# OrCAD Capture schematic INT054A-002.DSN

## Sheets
1 PAGE1: title: TUSB544RNQEVM INT054-002; rev: A
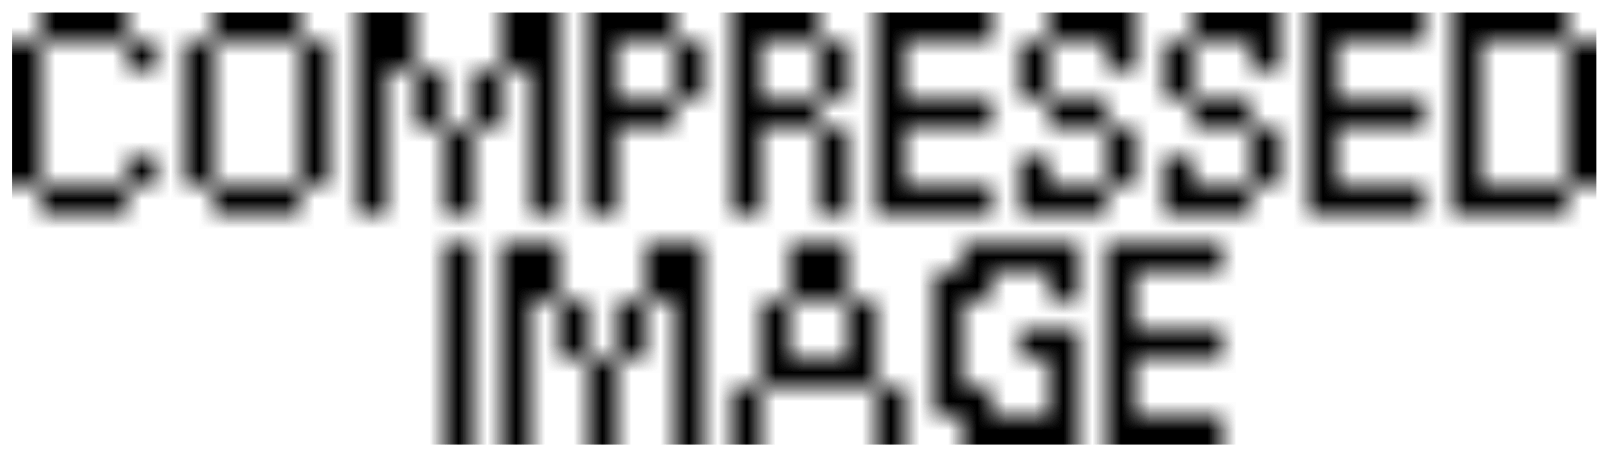
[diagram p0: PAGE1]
2 PAGE2: size C
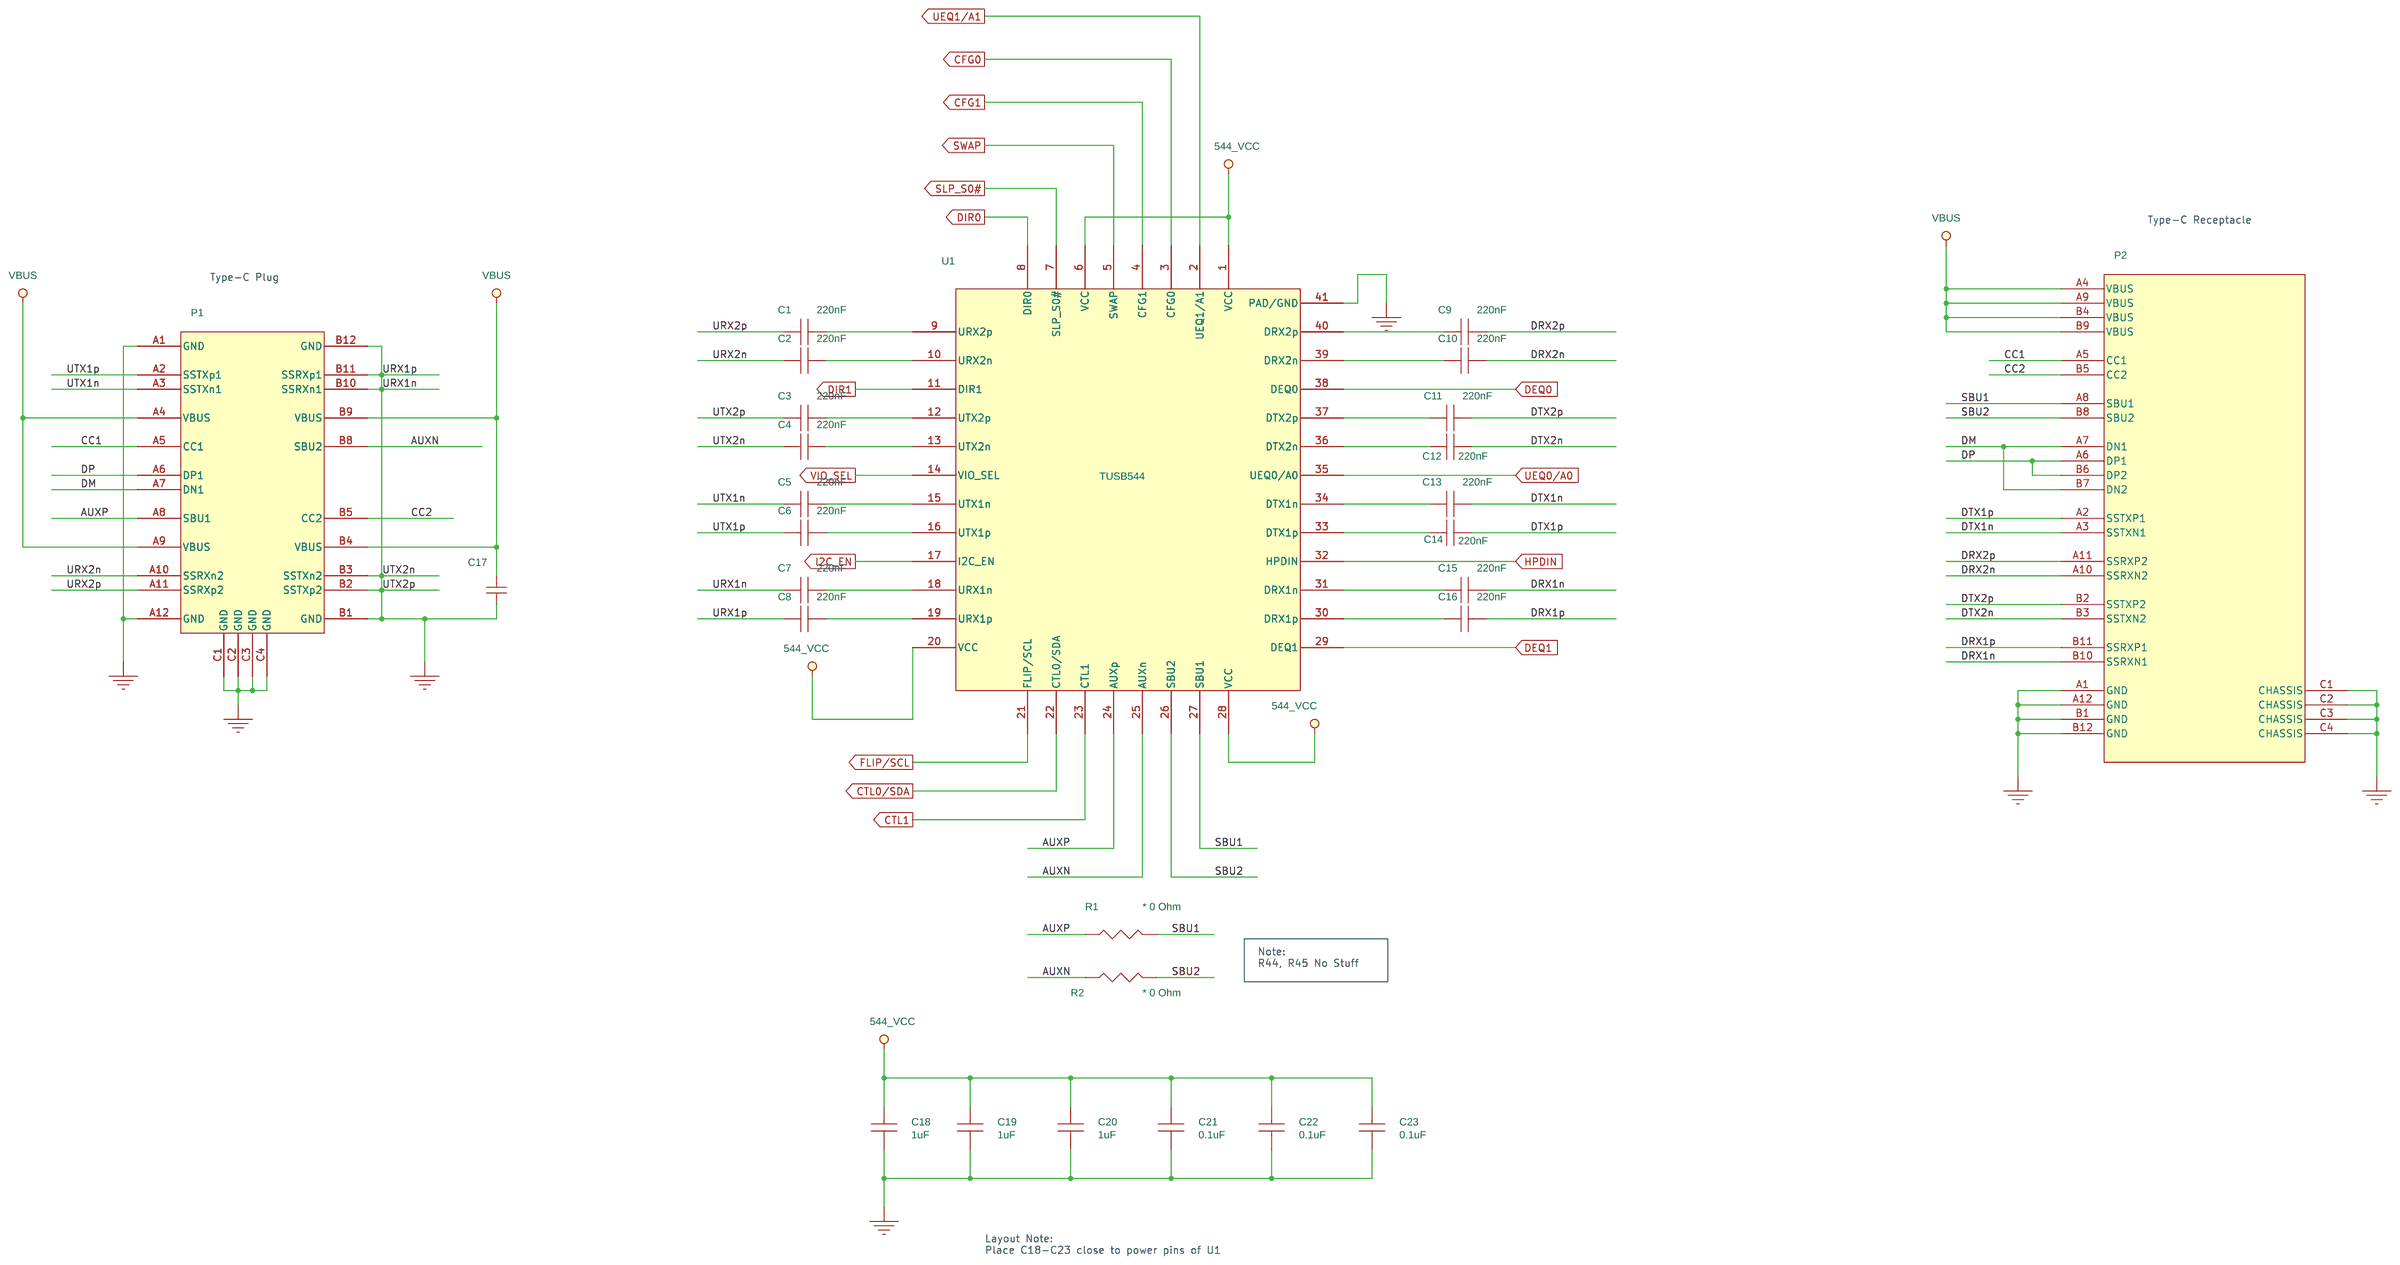
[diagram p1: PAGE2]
3 PAGE3: size C
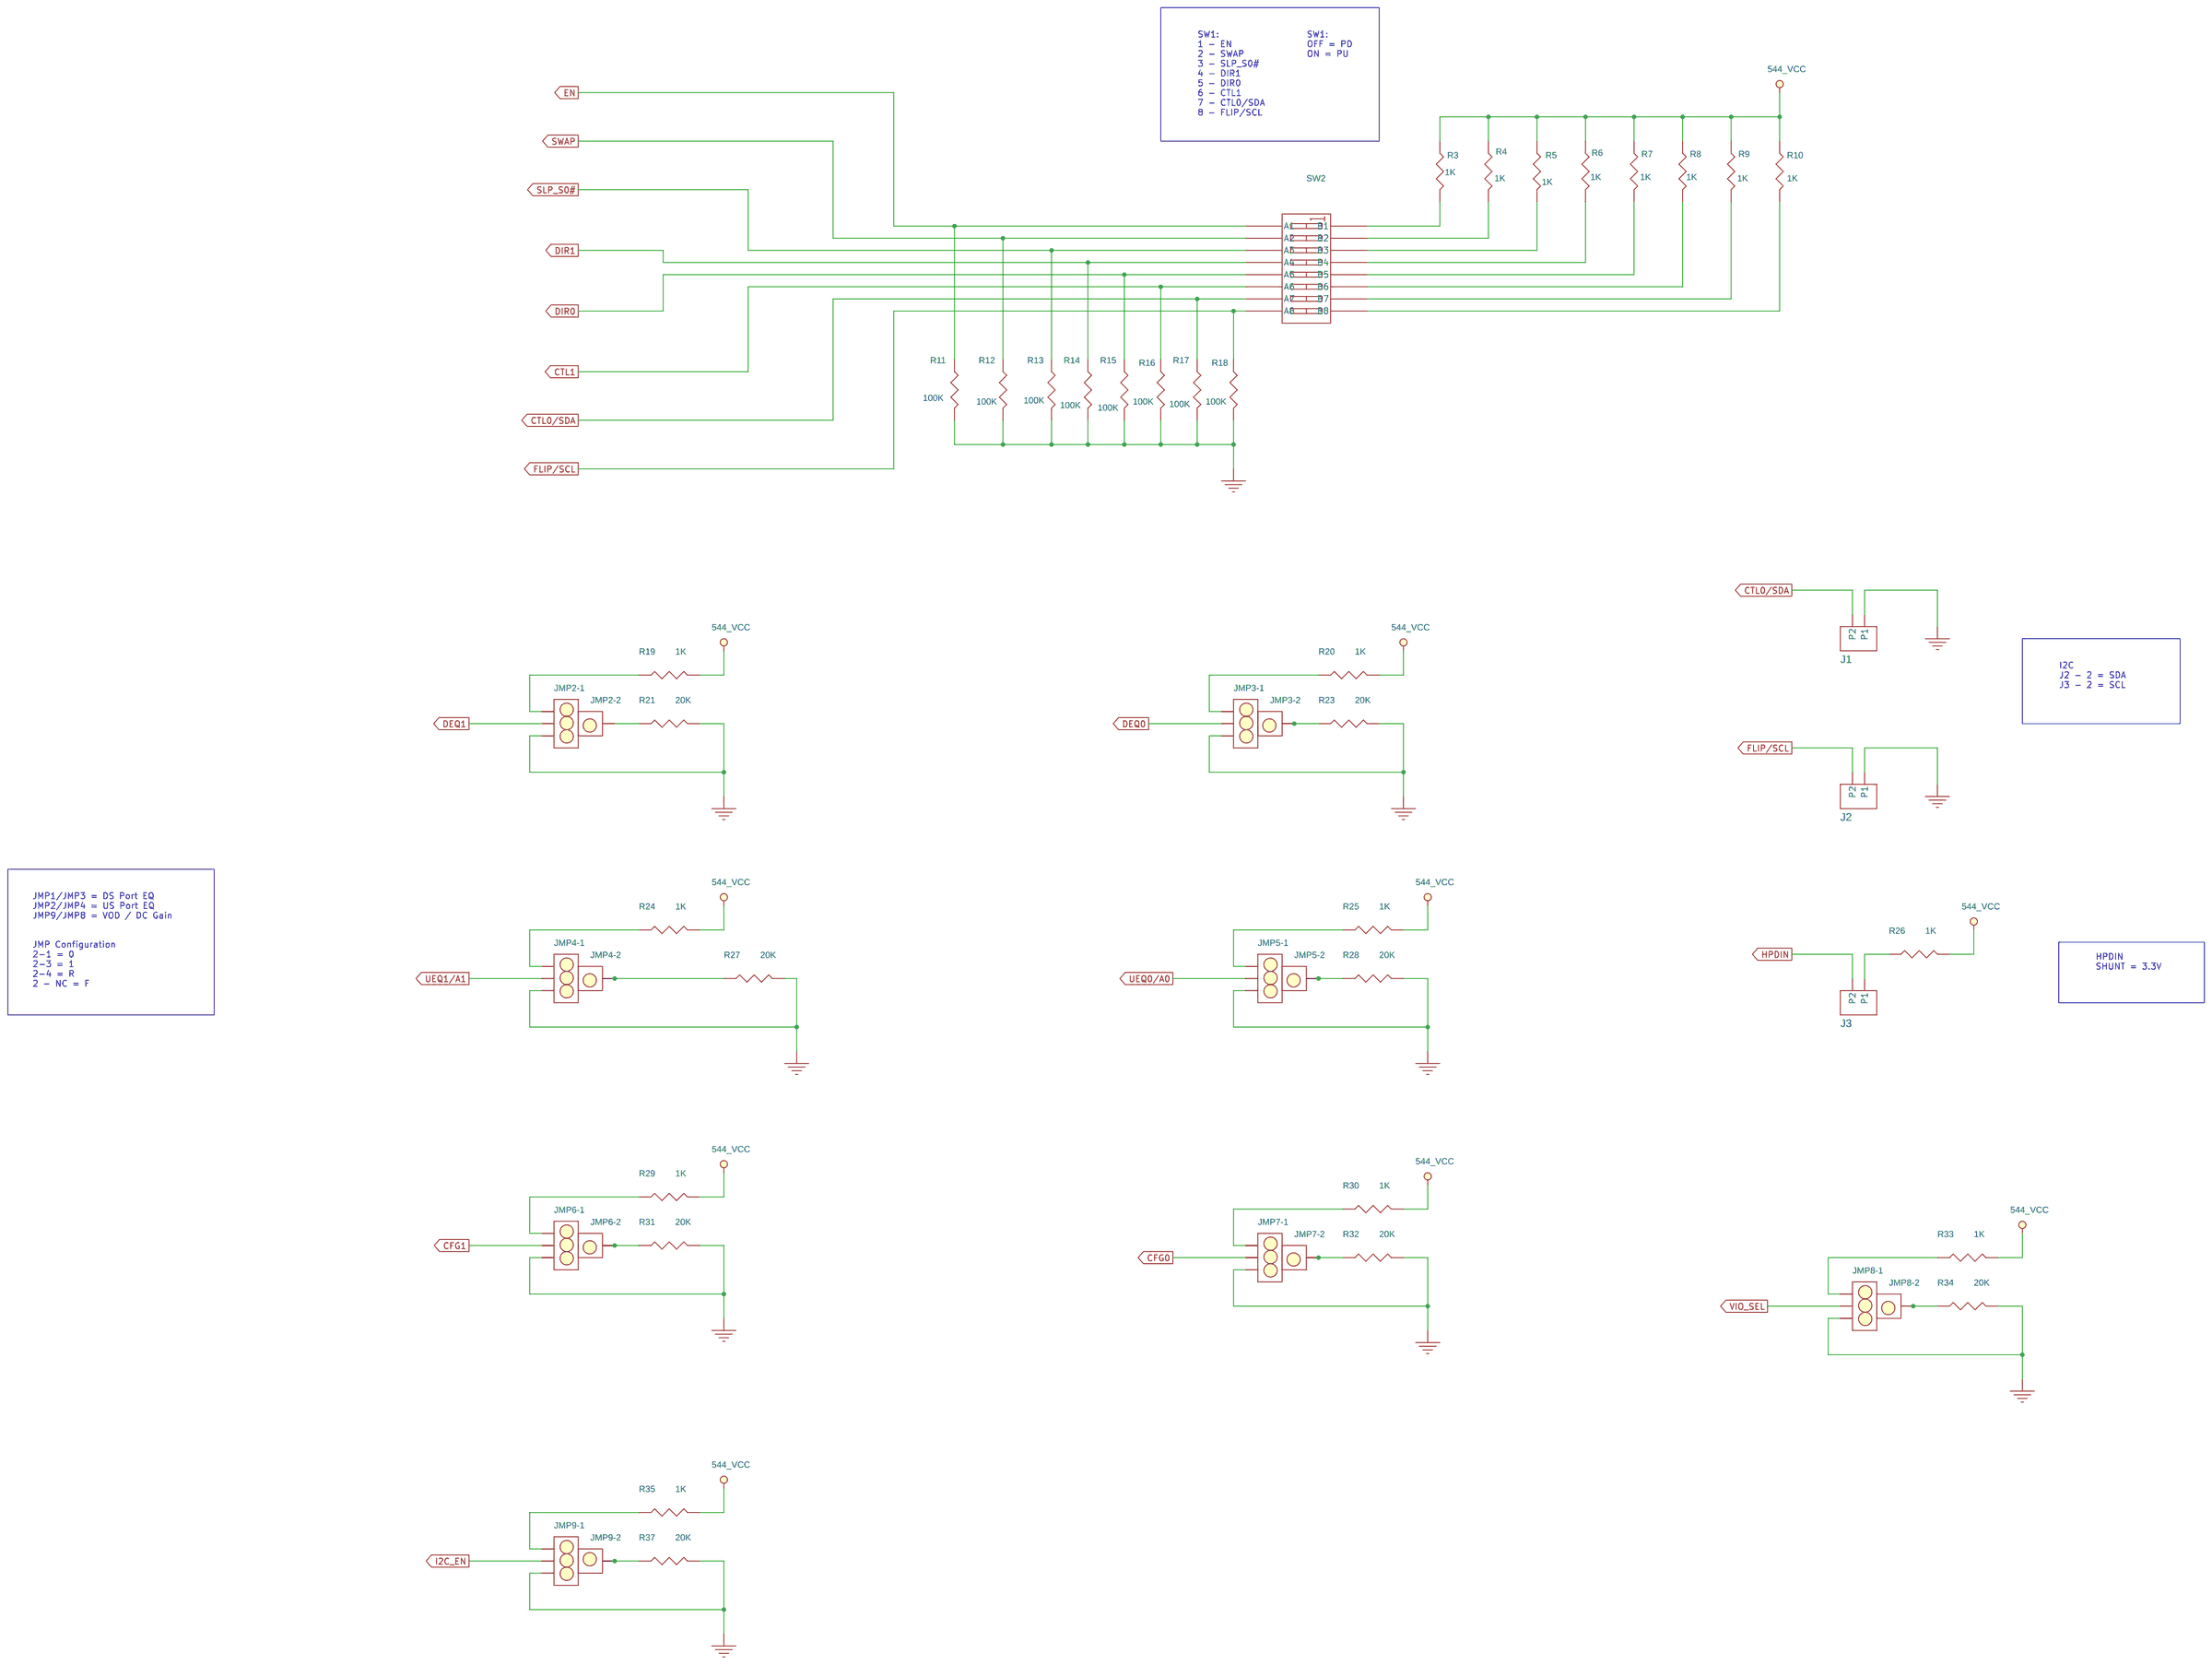
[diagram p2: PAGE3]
4 PAGE4: size C
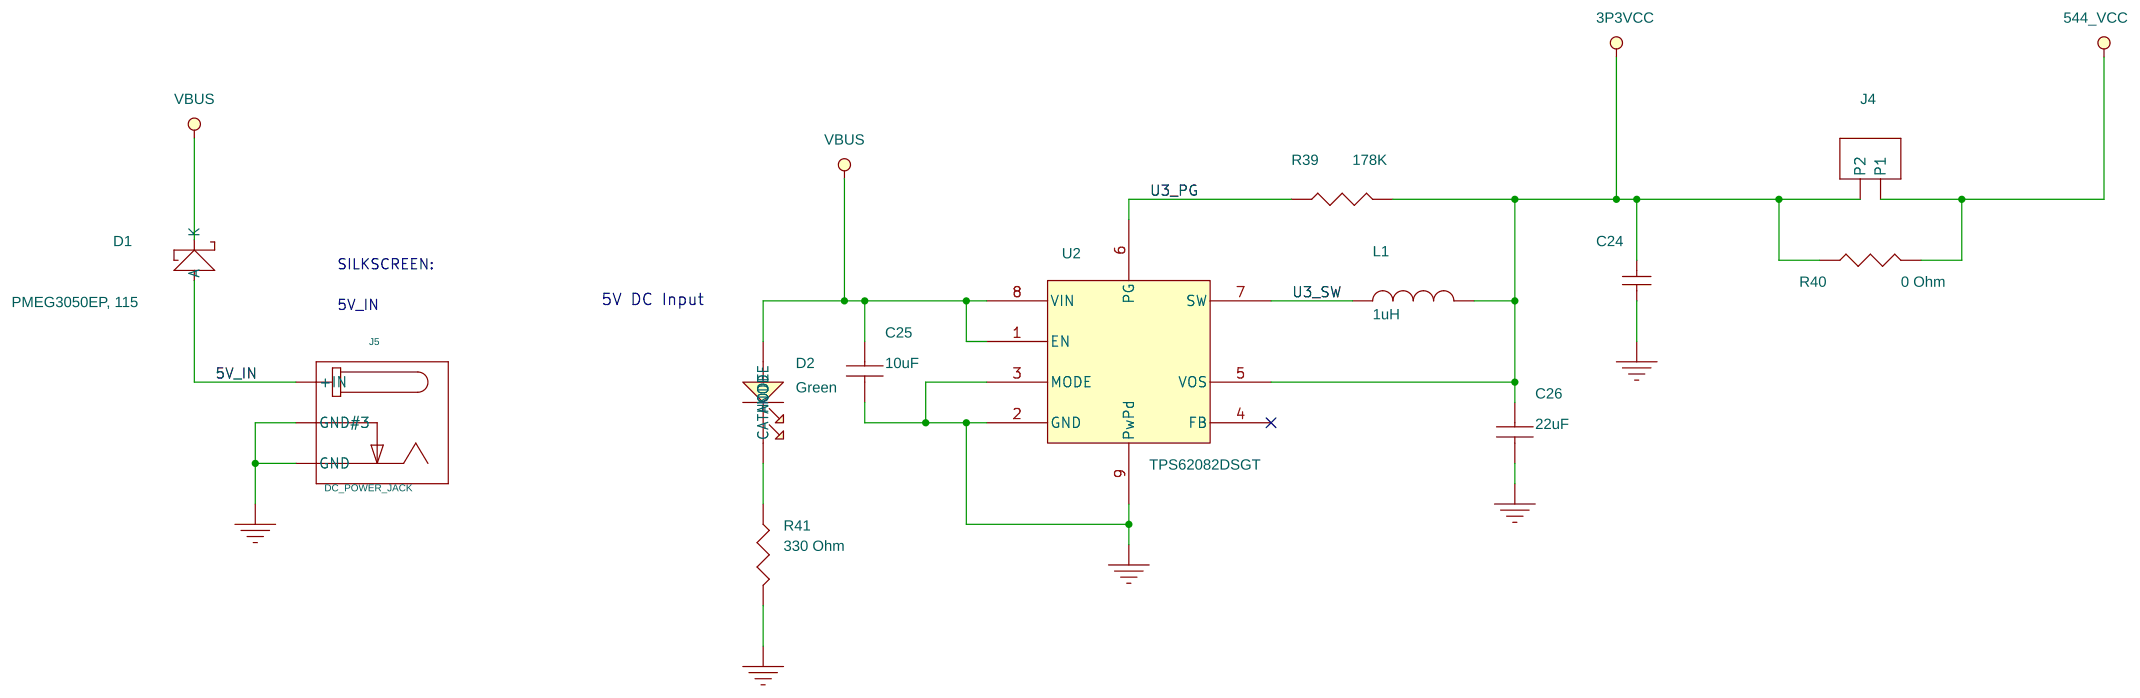
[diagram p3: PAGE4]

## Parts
sheet PAGE2
C1  220nF  [cc0201]
C2  220nF  [cc0201]
C3  220nF  [cc0201]
C4  220nF  [cc0201]
C5  220nF  [cc0201]
C6  220nF  [cc0201]
C7  220nF  [cc0201]
C8  220nF  [cc0201]
C9  220nF  [cc0201]
C10  220nF  [cc0201]
C11  220nF  [cc0201]
C12  220nF  [cc0201]
C13  220nF  [cc0201]
C14  220nF  [cc0201]
C15  220nF  [cc0201]
C16  220nF  [cc0201]
C17  10uF  [0805]
C18  1uF  [cc0402]
C19  1uF  [cc0402]
C20  1uF  [cc0402]
C21  0.1uF  [cc0402]
C22  0.1uF  [cc0402]
C23  0.1uF  [cc0402]
P1  Wurth 632712000021  [USB-C_SMRT_632_712_000_021]
P2  JAE DX07S024JJ2  [USB-C_SMRT_DX07S024JJ2]
R1  * 0 Ohm  [r0402]
R2  * 0 Ohm  [r0402]
U1  TUSB544  [SKT_IRONWOOD_C14861_QFN-40]
sheet PAGE3
J1  CON02  [HDR_THVT_1x2_100_M]
J2  CON02  [HDR_THVT_1x2_100_M]
J3  CON02  [HDR_THVT_1x2_100_M]
JMP2-1  JMP1x3  [berg1x3]
JMP2-2  JMP1x1  [berg1x1]
JMP3-1  JMP1x3  [berg1x3]
JMP3-2  JMP1x1  [berg1x1]
JMP4-1  JMP1x3  [berg1x3]
JMP4-2  JMP1x1  [berg1x1]
JMP5-1  JMP1x3  [berg1x3]
JMP5-2  JMP1x1  [berg1x1]
JMP6-1  JMP1x3  [berg1x3]
JMP6-2  JMP1x1  [berg1x1]
JMP7-1  JMP1x3  [berg1x3]
JMP7-2  JMP1x1  [berg1x1]
JMP8-1  JMP1x3  [berg1x3]
JMP8-2  JMP1x1  [berg1x1]
JMP9-1  JMP1x3  [berg1x3]
JMP9-2  4 Pin-T Berg Jumper  [berg1x1]
R3  1K  [r0402]
R4  1K  [r0402]
R5  1K  [r0402]
R6  1K  [r0402]
R7  1K  [r0402]
R8  1K  [r0402]
R9  1K  [r0402]
R10  1K  [r0402]
R11  100K  [r0402]
R12  100K  [r0402]
R13  100K  [r0402]
R14  100K  [r0402]
R15  100K  [r0402]
R16  100K  [r0402]
R17  100K  [r0402]
R18  100K  [r0402]
R19  1K  [r0402]
R20  1K  [r0402]
R21  20K  [r0402]
R23  20K  [r0402]
R24  1K  [r0402]
R25  1K  [r0402]
R26  1K  [r0402]
R27  20K  [r0402]
R28  20K  [r0402]
R29  1K  [r0402]
R30  1K  [r0402]
R31  20K  [r0402]
R32  20K  [r0402]
R33  1K  [r0402]
R34  20K  [r0402]
R35  1K  [r0402]
R37  20K  [r0402]
SW2  8-POS 50-MIL SMT  [SW_SMVT_SPST_TDA08]
sheet PAGE4
C24  10uF  [0805]
C25  10uF  [0805]
C26  22uF  [0805]
D1  SCHOTTKY  [diode_smb]
D2  Green  [LED0805]
J4  CON02  [berg1x2]
J5  DC_PWR_JACK  [pj-202ah]
L1  1uH  [IND_NR3015]
R39  178K  [r0402]
R40  0 Ohm  [r1206]
R41  330 Ohm  [r0603]
U2  TPS62082DSGT  [dsg]

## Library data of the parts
C1-C16 = cc0201
C17 C24 = CAP: 6.3V Capacitor; $SEC: 1; ATIPartNo: 4210010600G; CDS_LIB: capacitor; DRAWING: @LIGHTNING_BOLT_NB_LIB.NOTE_BOOK(SCH_1):PAGE1; PHYS_PAGE: 1; ROT: 0; TOLERANCE: 10%; VER: 1; VOLTAGE: 6.3V; XY: (-9500,3550)
C18-C23 = cc0402
P1 = Type_C_Plug_0
P2 = TypeC_JAE_TopMNT
R1-R21 R23-R35 R37 R39 = r0402
U1 = TUSB1044RNQ
J1-J4 = CON02: Header; ATIPartNo: 6010014900G; CDS_LIB: connector; DEVICE_NAME: BERG1X2; DRAWING: @LIGHTNING_BOLT_NB_LIB.NOTE_BOOK(SCH_1):PAGE2; Digi-Key Part Number: 609-3507-ND; Manufacturer: FCI; Manufacturer Part Number: 68001-402HLF; Manufacturer's Part Number: 68001-402HLF; PHYS_PAGE: 2; ROT: 5; VER: 1; XY: (-6100,5150)
JMP2-1 JMP3-1 JMP4-1 JMP5-1 JMP6-1 JMP7-1 JMP8-1 JMP9-1 = JMP1x3
JMP2-2 JMP3-2 JMP4-2 JMP5-2 JMP6-2 JMP7-2 JMP8-2 = JMP1x1
JMP9-2 = 4_Pin-T_Berg_Jumper_1
SW2 = SW_DIP-8_SM_0: Manuf: C&K(ITT-CANNON); Manuf PN: TDA08H0SK1R; Manufacturer: C&K(ITT-CANNON); Manufacturer Part Number: TDA08H0SK1R; Vendor: C&K (ITT-CANNON); Vendor Part Number: TDA08H0SK1R
C25 C26 = CAP_NP: 6.3V Capacitor
D1 = SCHOTTKY: Diode; $SEC: 1; CDS_LIB: diode; DEVICE_NAME: PMEG3050EP, 115; Digi-Key Part Number: 568-6753-2-ND; Manufacturer: NXP; Manufacturer Part Number: PMEG3050EP,115; Manufacturer's Part Number: PMEG3050EP,115; PHYS_PAGE: 1; ROT: 0; TOLERANCE: NA; VER: 1; VOLTAGE: 10V; XY: (-1750,3700)
D2 = Green_LED
J5 = 6140046600_DC_PWR_JACK: DC Power Jack; $SEC: 1; CDS_LIB: connector; DEVICE_NAME: DC_POWER_JACK; DRAWING: @LIGHTNING_BOLT_NB_LIB.NOTE_BOOK(SCH_1):PAGE2; Digi-Key Part Number: CP-202AH-ND; GroupName: COMMON; Manuf: CUI Inc.; Manuf PN: PJ-202AH; Manufacturer: CUI Inc.; Manufacturer Part Number: PJ-202AH; Manufacturer's Part Number: PJ-202AH; PHYS_PAGE: 2; ROT: 0; VER: 1; XY: (-4550,4450)
L1 = INDUCTOR: Inductor; CDS_LIB: Inductor; Digi-Key Part Number: 587-1647-1-ND; Manuf: Taiyo Yuden; Manuf PN: NR3015T1R0N; Manufacturer: Taiyo Yuden; Manufacturer Part Number: NR3015T1R0N; Manufacturer's Part Number: NR3015T1R0N
R40 = r1206
R41 = r0603
U2 = TPS62082: DC/DC Converter; Digi-Key Part Number: 296-29647-1-ND; Manuf: Texas Instruments; Manufacturer: Texas Instruments

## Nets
5V_IN: D1.2(A) J5.1(+IN)
GND: C17.2(B) C18.2 C19.2 C20.2 C21.2 C22.2 C23.2 C24.2(B) C25.2 C26.2 J1.1(P1) J2.1(P1) J5.2(GND) J5.3(GND#3) JMP2-1.3 JMP3-1.3 JMP4-1.3 JMP5-1.3 JMP6-1.3 JMP7-1.3 JMP8-1.3 JMP9-1.3 P1.A1(GND) P1.A12(GND) P1.B1(GND) P1.B12(GND) P1.C1(GND) P1.C2(GND) P1.C3(GND) P1.C4(GND) P2.A1(GND) P2.A12(GND) P2.B1(GND) P2.B12(GND) P2.C1(CHASSIS) P2.C2(CHASSIS) P2.C3(CHASSIS) P2.C4(CHASSIS) R11.2 R12.2 R13.2 R14.2 R15.2 R16.2 R17.2 R18.2 R21.2 R23.2 R27.2 R28.2 R31.2 R32.2 R34.2 R37.2 R41.2 U1.41(PAD/GND) U2.2(GND) U2.3(MODE) U2.9(PwPd)
VBUS: C17.1(A) C25.1 D1.1(K) D2.2(ANODE) P1.A4(VBUS) P1.A9(VBUS) P1.B4(VBUS) P1.B9(VBUS) P2.A4(VBUS) P2.A9(VBUS) P2.B4(VBUS) P2.B9(VBUS) U2.1(EN) U2.8(VIN)
3P3VCC: C24.1(A) C26.1 J4.2(P2) L1.2 R39.2 R40.1 U2.5(VOS)
544_VCC: C18.1 C19.1 C20.1 C21.1 C22.1 C23.1 J4.1(P1) R3.1 R4.1 R5.1 R6.1 R7.1 R8.1 R9.1 R10.1 R19.2 R20.2 R24.2 R25.2 R26.2 R29.2 R30.2 R33.2 R35.2 R40.2 U1.1(VCC) U1.6(VCC) U1.20(VCC) U1.28(VCC)
AUXN: P1.B8(SBU2) R2.1 U1.25(AUXn)
AUXP: P1.A8(SBU1) R1.1 U1.24(AUXp)
CC1: P1.A5(CC1) P2.A5(CC1)
CC2: P1.B5(CC2) P2.B5(CC2)
CFG0: JMP7-1.2 U1.3(CFG0)
CFG1: JMP6-1.2 U1.4(CFG1)
CTL0/SDA: J1.2(P2) R17.1 SW2.7(A7) U1.22(CTL0/SDA)
CTL1: R16.1 SW2.6(A6) U1.23(CTL1)
DEQ0: JMP3-1.2 U1.38(DEQ0)
DEQ1: JMP2-1.2 U1.29(DEQ1)
DIR0: R15.1 SW2.5(A5) U1.8(DIR0)
DIR1: R14.1 SW2.4(A4) U1.11(DIR1)
DM: P1.A7(DN1) P2.A7(DN1) P2.B7(DN2)
DP: P1.A6(DP1) P2.A6(DP1) P2.B6(DP2)
DRX1n: C15.2 P2.B10(SSRXN1)
DRX1p: C16.2 P2.B11(SSRXP1)
DRX2n: C10.2 P2.A10(SSRXN2)
DRX2p: C9.2 P2.A11(SSRXP2)
DTX1n: C13.2 P2.A3(SSTXN1)
DTX1p: C14.2 P2.A2(SSTXP1)
DTX2n: C12.2 P2.B3(SSTXN2)
DTX2p: C11.2 P2.B2(SSTXP2)
EN: R11.1 SW2.1(A1)
FLIP/SCL: J2.2(P2) R18.1 SW2.8(A8) U1.21(FLIP/SCL)
HPDIN: J3.2(P2) U1.32(HPDIN)
I2C_EN: JMP9-1.2 U1.17(I2C_EN)
SBU1: P2.A8(SBU1) R1.2 U1.27(SBU1)
SBU2: P2.B8(SBU2) R2.2 U1.26(SBU2)
SLP_S0#: R13.1 SW2.3(A3) U1.7(SLP_S0#)
SWAP: R12.1 SW2.2(A2) U1.5(SWAP)
U3_PG: R39.1 U2.6(PG)
U3_SW: L1.1 U2.7(SW)
UEQ0/A0: JMP5-1.2 U1.35(UEQ0/A0)
UEQ1/A1: JMP4-1.2 U1.2(UEQ1/A1)
URX1n: C7.1 P1.B10(SSRXn1)
URX1p: C8.1 P1.B11(SSRXp1)
URX2n: C2.1 P1.A10(SSRXn2)
URX2p: C1.1 P1.A11(SSRXp2)
UTX1n: C5.1 P1.A3(SSTXn1)
UTX1p: C6.1 P1.A2(SSTXp1)
UTX2n: C4.1 P1.B3(SSTXn2)
UTX2p: C3.1 P1.B2(SSTXp2)
VIO_SEL: JMP8-1.2 U1.14(VIO_SEL)
N02046: C1.2 U1.9(URX2p)
N02050: C2.2 U1.10(URX2n)
N02054: C3.2 U1.12(UTX2p)
N02058: C4.2 U1.13(UTX2n)
N02062: C5.2 U1.15(UTX1n)
N02066: C6.2 U1.16(UTX1p)
N02070: C7.2 U1.18(URX1n)
N02074: C8.2 U1.19(URX1p)
N02276: C9.1 U1.40(DRX2p)
N02280: C10.1 U1.39(DRX2n)
N02284: C11.1 U1.37(DTX2p)
N02288: C12.1 U1.36(DTX2n)
N02292: C13.1 U1.34(DTX1n)
N02296: C14.1 U1.33(DTX1p)
N02300: C15.1 U1.31(DRX1n)
N02304: C16.1 U1.30(DRX1p)
N06058: R3.2 SW2.16(B1)
N06065: R4.2 SW2.15(B2)
N06072: R5.2 SW2.14(B3)
N06079: R6.2 SW2.13(B4)
N06086: R7.2 SW2.12(B5)
N06093: R8.2 SW2.11(B6)
N06100: R9.2 SW2.10(B7)
N06107: R10.2 SW2.9(B8)
N06374: JMP2-1.1 R19.1
N06386: JMP2-2.1 R21.1
N06671: JMP4-1.1 R24.1
N06683: JMP4-2.1 R27.1
N06999: JMP3-1.1 R20.1
N07011: JMP3-2.1 R23.1
N07344: JMP5-1.1 R25.1
N07356: JMP5-2.1 R28.1
N08061: JMP8-1.1 R33.1
N08073: JMP8-2.1 R34.1
N08437: JMP9-1.1 R35.1
N08449: JMP9-2.1 R37.1
N08820: JMP7-1.1 R30.1
N08832: JMP7-2.1 R32.1
N09158: J3.1(P1) R26.1
N09488: JMP6-1.1 R29.1
N15413: D2.1(CATHODE) R41.1
N46287: JMP6-2.1 R31.1

Not connected (* = marked no-connect by the designer): U2 4(FB)*

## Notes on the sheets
sheet 2
- Type-C Receptacle
- Type-C Plug
- Note:
  R44, R45 No Stuff
- Layout Note:
  Place C18-C23 close to power pins of U1
sheet 3
- SW1:
  1 - EN
  2 - SWAP
  3 - SLP_S0#
  4 - DIR1
  5 - DIR0
  6 - CTL1
  7 - CTL0/SDA
  8 - FLIP/SCL
- SW1:
  OFF = PD
  ON = PU
- I2C
  J2 - 2 = SDA
  J3 - 2 = SCL
- JMP1/JMP3 = DS Port EQ
  JMP2/JMP4 = US Port EQ
  JMP9/JMP8 = VOD / DC Gain
- JMP Configuration
  2-1 = 0
  2-3 = 1
  2-4 = R
  2 - NC = F
- HPDIN
  SHUNT = 3.3V
sheet 4
- SILKSCREEN:
- 5V_IN
- 5V DC Input
